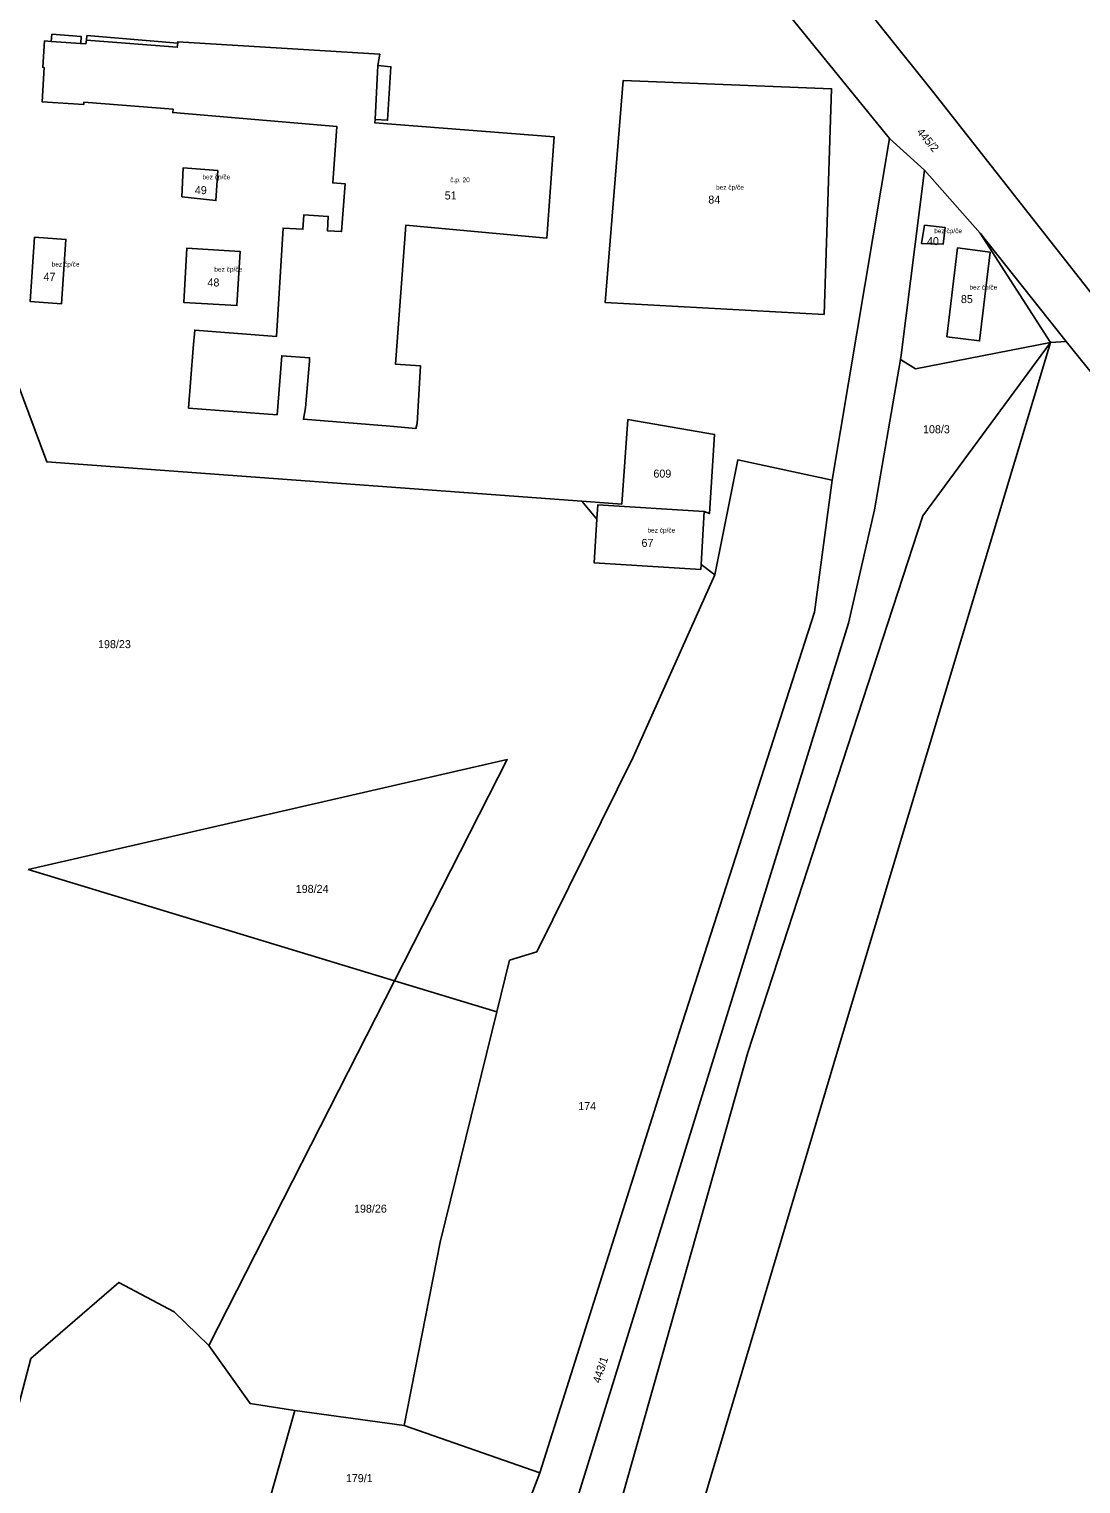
# Model space of a CAD drawing. Extents: x -882150 to -879379, y -1022570 to -1019819.
# Drawn here: x -880262.5 to -880039.3, y -1020448.8 to -1020139.9 of the extents above; entities that cross this region are included whole.
import ezdxf

# ---------------------------------------------------------------- set-up
doc = ezdxf.new("R2010")
doc.units = 0
for name, color, linetype in [('Definiční body', 7, 'Continuous'), ('Hranice parcel', 7, 'Continuous'), ('Parcelní čísla', 7, 'Continuous'), ('Polygon budovy', 7, 'Continuous'), ('Vnitřní kresba', 7, 'Continuous')]:
    doc.layers.add(name, color=color, linetype=linetype)

msp = doc.modelspace()

# ---------------------------------------------------------------- linework, layer by layer
at = {"layer": 'Hranice parcel'}
for p, q in [((-880092.08, -1020235.63), (-880079.85, -1020163.08)), ((-880072.45, -1020169.8), (-880079.85, -1020163.08)), ((-880090.68, -1020356.2), (-880045.71, -1020206.44)), ((-880045.71, -1020206.44), (-880042.35, -1020206.21)), ((-880185.86, -1020224.16), (-880180.44, -1020224.69)), ((-880141.97, -1020243.96), (-880145.16, -1020240.12)), ((-880119.87, -1020253.55), (-880119.19, -1020242.28)), ((-880119.87, -1020253.55), (-880116.97, -1020255.76)), ((-880262.73, -1020318.32), (-880184.91, -1020341.96)), ((-880224.37, -1020419.46), (-880184.91, -1020341.96)), ((-880184.91, -1020341.96), (-880163.22, -1020348.55)), ((-880206.12, -1020433.27), (-880215.14, -1020465.24)), ((-880182.9, -1020436.43), (-880206.12, -1020433.27)), ((-880182.9, -1020436.43), (-880154.08, -1020446.48)), ((-880167, -1020480.4), (-880154.08, -1020446.48))]:
    msp.add_line(p, q, dxfattribs=at)
for points in [[(-880163.65, -1020039.32), (-880129.35, -1020080.97), (-880116.9, -1020095.84), (-880103.23, -1020112.38), (-880070.49, -1020153.39), (-880028.73, -1020206.59)], [(-880079.85, -1020163.08), (-880116.94, -1020117.46), (-880128.9, -1020103.08)], [(-880250.46, -1020143), (-880251.55, -1020142.92), (-880251.42, -1020141.46), (-880257.66, -1020140.95), (-880257.8, -1020142.46), (-880259.26, -1020142.35), (-880259.6, -1020147.96), (-880259.31, -1020148), (-880259.75, -1020155.28), (-880250.91, -1020155.86), (-880250.88, -1020155.4), (-880231.94, -1020156.84), (-880232, -1020157.58)], [(-880250.27, -1020141.21), (-880250.35, -1020142.23), (-880250.46, -1020143)], [(-880230.94, -1020142.57), (-880230.96, -1020142.81), (-880250.27, -1020141.21)], [(-880182.51, -1020181.47), (-880152.59, -1020184.24), (-880151.07, -1020162.72), (-880189.12, -1020159.73), (-880189.08, -1020159.08), (-880186.4, -1020159.21), (-880185.71, -1020147.84), (-880188.51, -1020147.62), (-880188.06, -1020145.19), (-880230.94, -1020142.57)], [(-880140.25, -1020197.9), (-880136.43, -1020150.78), (-880092.16, -1020152.51), (-880093.77, -1020200.46), (-880140.25, -1020197.9)], [(-880232, -1020157.58), (-880197.16, -1020160.55), (-880198.04, -1020172.53), (-880195.41, -1020172.75), (-880196.16, -1020182.86)], [(-880229.77, -1020169.3), (-880230.08, -1020175.45), (-880222.86, -1020176.28), (-880222.46, -1020169.89), (-880229.77, -1020169.3)], [(-880072.45, -1020169.8), (-880077.38, -1020209.12), (-880077.54, -1020210.05)], [(-880042.35, -1020206.21), (-880060.6, -1020183.2), (-880072.45, -1020169.8)], [(-880196.16, -1020182.86), (-880199.17, -1020182.68), (-880198.99, -1020179.63), (-880204.19, -1020179.32), (-880204.37, -1020182.37), (-880208.6, -1020182.12), (-880209.97, -1020205.13), (-880227.34, -1020203.79), (-880227.69, -1020207.65), (-880228.65, -1020220.35), (-880209.87, -1020221.77), (-880208.89, -1020209.22), (-880202.95, -1020209.66)], [(-880179.41, -1020211.39), (-880184.76, -1020211), (-880182.51, -1020181.47)], [(-880254.68, -1020184.54), (-880261.35, -1020184.05), (-880262.26, -1020197.71), (-880255.63, -1020198.24), (-880254.68, -1020184.54)], [(-880217.69, -1020187.09), (-880229, -1020186.35), (-880229.67, -1020197.9), (-880218.4, -1020198.56), (-880217.69, -1020187.09)], [(-880065.48, -1020186.34), (-880067.69, -1020205.21), (-880060.76, -1020206.08), (-880058.52, -1020187.24), (-880065.48, -1020186.34)], [(-880275.21, -1020187.64), (-880258.76, -1020231.77), (-880145.16, -1020240.12)], [(-880045.71, -1020206.44), (-880072.78, -1020243.25), (-880109.94, -1020357.24), (-880136.37, -1020450.63), (-880147.18, -1020488.43), (-880162.39, -1020532.15), (-880169.37, -1020529.41)], [(-880077.54, -1020210.05), (-880074.37, -1020212.03), (-880045.71, -1020206.44)], [(-879898.06, -1020548.48), (-879913.62, -1020520.69), (-879924.52, -1020497.9), (-879931.26, -1020476.35), (-879934.19, -1020461.7), (-879938.41, -1020420.22), (-879947.88, -1020362.58), (-879952, -1020338.2), (-879958.23, -1020317.82), (-879965.31, -1020303.46), (-879975.02, -1020294.36), (-880006.56, -1020250.49), (-880042.35, -1020206.21)], [(-880202.95, -1020209.66), (-880202.98, -1020210.39), (-880203.86, -1020220.29), (-880204.28, -1020222.71), (-880185.86, -1020224.16)], [(-880077.54, -1020210.05), (-880083.07, -1020241.93), (-880088.6, -1020266), (-880146.1, -1020451.8), (-880163.01, -1020510.18), (-880169.37, -1020529.41)], [(-880180.44, -1020224.69), (-880180.16, -1020223.62), (-880179.41, -1020211.39)], [(-880145.16, -1020240.12), (-880136.7, -1020240.74), (-880135.42, -1020222.79)], [(-880135.42, -1020222.79), (-880117.02, -1020225.94), (-880118.1, -1020242.75), (-880119.19, -1020242.28)], [(-880116.97, -1020255.76), (-880112.07, -1020231.35), (-880092.08, -1020235.63)], [(-880154.08, -1020446.48), (-880124.5, -1020352.98), (-880095.83, -1020263.71), (-880092.08, -1020235.63)], [(-880119.19, -1020242.28), (-880141.79, -1020240.92), (-880141.97, -1020243.96)], [(-880141.97, -1020243.96), (-880142.53, -1020253.23), (-880119.93, -1020254.6), (-880119.87, -1020253.55)], [(-880116.97, -1020255.76), (-880134.25, -1020294.46), (-880154.74, -1020335.85), (-880160.52, -1020337.61), (-880163.22, -1020348.55)], [(-880184.91, -1020341.96), (-880161, -1020295), (-880262.73, -1020318.32)], [(-880163.22, -1020348.55), (-880175.28, -1020397.52), (-880182.9, -1020436.43)], [(-880181.75, -1020778.37), (-880224.49, -1020805.59), (-880179.88, -1020655.79), (-880135.29, -1020506), (-880090.68, -1020356.2)], [(-880224.37, -1020419.46), (-880231.68, -1020412.27), (-880243.47, -1020406.04), (-880262.13, -1020422.22), (-880266.61, -1020439.29), (-880273.4, -1020507.16), (-880285.17, -1020537.62), (-880295.63, -1020564.31)], [(-880206.12, -1020433.27), (-880215.58, -1020431.77), (-880224.37, -1020419.46)]]:
    msp.add_lwpolyline(points, dxfattribs=at)
at = {"layer": 'Polygon budovy'}
for points in [[(-880204.28, -1020222.71), (-880185.86, -1020224.16), (-880180.44, -1020224.69), (-880180.16, -1020223.62), (-880179.41, -1020211.39), (-880184.76, -1020211), (-880182.51, -1020181.47), (-880152.59, -1020184.24), (-880151.07, -1020162.72), (-880189.12, -1020159.73), (-880189.08, -1020159.08), (-880188.51, -1020147.62), (-880188.06, -1020145.19), (-880230.94, -1020142.57), (-880230.96, -1020142.81), (-880231.04, -1020143.7), (-880250.35, -1020142.23), (-880250.46, -1020143), (-880251.55, -1020142.92), (-880257.8, -1020142.46), (-880259.26, -1020142.35), (-880259.6, -1020147.96), (-880259.31, -1020148), (-880259.75, -1020155.28), (-880250.91, -1020155.86), (-880250.88, -1020155.4), (-880231.94, -1020156.84), (-880232, -1020157.58), (-880197.16, -1020160.55), (-880198.04, -1020172.53), (-880195.41, -1020172.75), (-880196.16, -1020182.86), (-880199.17, -1020182.68), (-880198.99, -1020179.63), (-880204.19, -1020179.32), (-880204.37, -1020182.37), (-880208.6, -1020182.12), (-880209.97, -1020205.13), (-880227.34, -1020203.79), (-880227.69, -1020207.65), (-880228.65, -1020220.35), (-880209.87, -1020221.77), (-880208.89, -1020209.22), (-880202.95, -1020209.66), (-880202.98, -1020210.39), (-880203.86, -1020220.29)], [(-880092.16, -1020152.51), (-880136.43, -1020150.78), (-880140.25, -1020197.9), (-880093.77, -1020200.46)], [(-880222.86, -1020176.28), (-880222.46, -1020169.89), (-880229.77, -1020169.3), (-880230.08, -1020175.45)], [(-880072.45, -1020181.51), (-880073.12, -1020185.36), (-880068.5, -1020185.54), (-880068.05, -1020182)], [(-880262.26, -1020197.71), (-880255.63, -1020198.24), (-880254.68, -1020184.54), (-880261.35, -1020184.05)], [(-880218.4, -1020198.56), (-880217.69, -1020187.09), (-880229, -1020186.35), (-880229.67, -1020197.9)], [(-880065.48, -1020186.34), (-880067.69, -1020205.21), (-880060.76, -1020206.08), (-880058.52, -1020187.24)], [(-880119.87, -1020253.55), (-880119.19, -1020242.28), (-880141.79, -1020240.92), (-880141.97, -1020243.96), (-880142.53, -1020253.23), (-880119.93, -1020254.6)]]:
    msp.add_lwpolyline(points, close=True, dxfattribs=at)
at = {"layer": 'Vnitřní kresba'}
for p, q in [((-880257.8, -1020142.46), (-880251.55, -1020142.92)), ((-880231.04, -1020143.7), (-880250.35, -1020142.23)), ((-880230.96, -1020142.81), (-880231.04, -1020143.7)), ((-880188.51, -1020147.62), (-880189.08, -1020159.08)), ((-880073.12, -1020185.36), (-880072.45, -1020181.51)), ((-880072.45, -1020181.51), (-880068.05, -1020182)), ((-880068.05, -1020182), (-880068.5, -1020185.54)), ((-880060.6, -1020183.2), (-880045.71, -1020206.44)), ((-880073.12, -1020185.36), (-880068.5, -1020185.54))]:
    msp.add_line(p, q, dxfattribs=at)

# ---------------------------------------------------------------- texts
at = {"layer": 'Definiční body'}
for s, p in [('bez čp/če', (-880225.71, -1020171.76)), ('č.p. 20', (-880173.11, -1020172.37)), ('bez čp/če', (-880116.69, -1020173.96)), ('bez čp/če', (-880070.39, -1020183.2)), ('bez čp/če', (-880257.71, -1020190.3)), ('bez čp/če', (-880223.18, -1020191.37)), ('bez čp/če', (-880062.91, -1020195.19)), ('bez čp/če', (-880131.26, -1020246.78))]:
    msp.add_text(s, height=1, dxfattribs=at).set_placement(p)
at = {"layer": 'Parcelní čísla'}
for s, rotation, p in [('445/2', 310, (-880074.211, -1020161.786)), ('443/1', 72, (-880141.321, -1020427.552))]:
    msp.add_text(s, height=1.7, rotation=rotation, dxfattribs=at).set_placement(p)
for s, p in [('49', (-880227.31, -1020174.91)), ('51', (-880174.28, -1020176.04)), ('84', (-880118.337, -1020176.92)), ('40', (-880071.92, -1020185.74)), ('47', (-880259.44, -1020193.32)), ('48', (-880224.64, -1020194.52)), ('85', (-880064.721, -1020198.05)), ('108/3', (-880072.76, -1020225.69)), ('609', (-880129.992, -1020235.11)), ('67', (-880132.51, -1020249.83)), ('198/23', (-880247.86, -1020271.33)), ('198/24', (-880205.9, -1020323.31)), ('174', (-880145.94, -1020369.44)), ('198/26', (-880193.53, -1020391.22)), ('179/1', (-880195.26, -1020448.46))]:
    msp.add_text(s, height=1.7, dxfattribs=at).set_placement(p)

doc.saveas('drawing.dxf')
